// Mitsubishi GX Works2 project: Comunicação   PLC: FX3U/FX3UC

PROGRAM MAIN
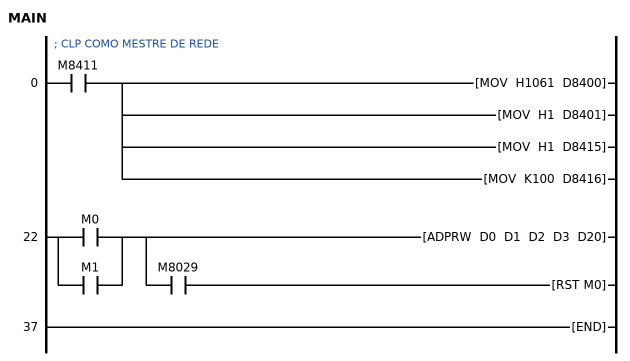
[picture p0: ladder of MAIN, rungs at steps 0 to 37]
; CLP COMO MESTRE DE REDE
0     LD      M8411
      MOV     H1061 D8400
      MOV     H1 D8401
      MOV     H1 D8415
      MOV     K100 D8416
22    LD      M0
      OR      M1
      ADPRW   D0 D1 D2 D3 D20
      AND     M8029
      RST     M0
37    END
END_PROGRAM
